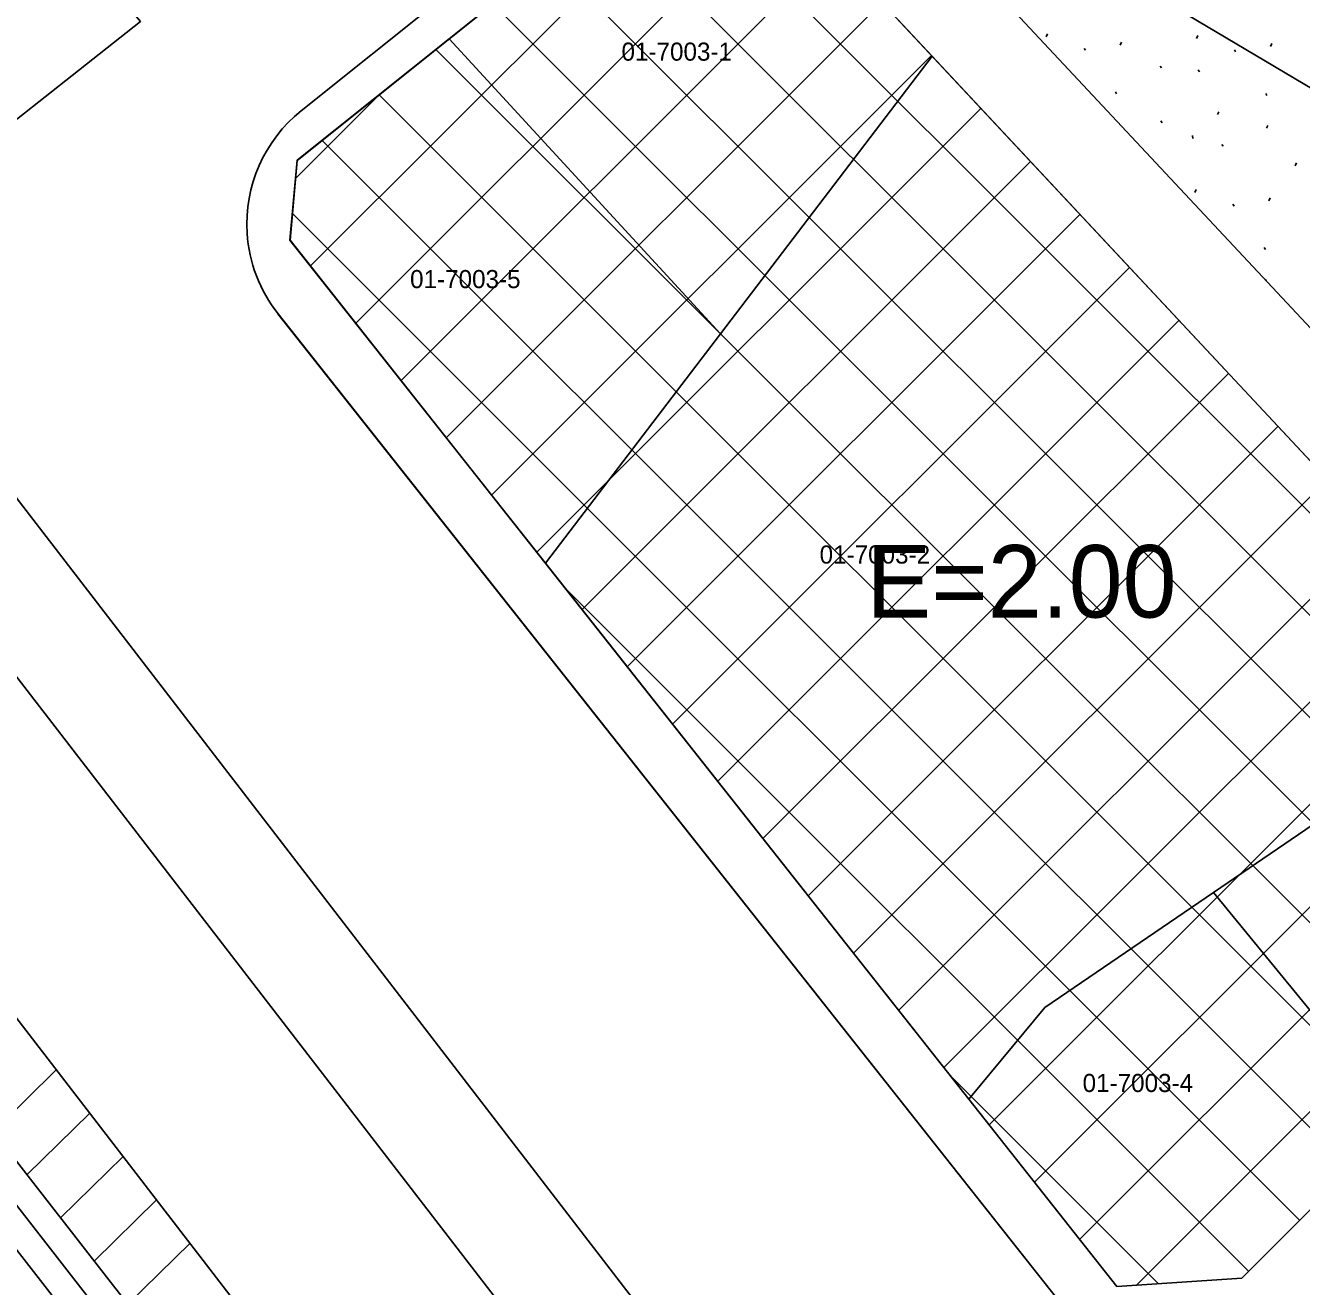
# Model space of a CAD drawing. Extents: x 413946 to 415528, y 4453939 to 4454944.
# Drawn here: x 414666.5 to 414736.9, y 4454622.3 to 4454691.9 of the extents above; entities that cross this region are included whole.
import ezdxf

# ---------------------------------------------------------------- set-up
doc = ezdxf.new("R2010")
doc.units = 0
for name, color, linetype in [('0_KADASTRO', 7, 'Continuous'), ('Level 28', 7, 'Continuous'), ('Level 29', 7, 'Continuous'), ('Level 30', 7, 'Continuous'), ('Level 34', 7, 'Continuous'), ('Level 41', 7, 'Continuous'), ('Level 53', 7, 'Continuous'), ('Level 62', 7, 'Continuous')]:
    doc.layers.add(name, color=color, linetype=linetype)

msp = doc.modelspace()

# ---------------------------------------------------------------- linework, layer by layer
at = {"layer": '0_KADASTRO'}
for points in [[(414705.59, 4454707.32), (414711.53, 4454711.44), (414720.94, 4454716.78), (414737.42, 4454727.23), (414744.54, 4454719.51), (414749.84, 4454713.87), (414763.53, 4454699.29), (414766.996, 4454695.593), (414767.59, 4454694.96), (414753, 4454679.16)], [(414689.88, 4454691.13), (414704.62, 4454702.92), (414716.53, 4454690.17), (414704.85, 4454674.85)], [(414654.74, 4454690.35), (414658.55, 4454693.35), (414666.43, 4454699.58), (414672.85, 4454692.09), (414660.82, 4454682.59)], [(414681.1, 4454680.02), (414681.5, 4454684.42), (414689.88, 4454691.13), (414704.85, 4454674.85), (414695.19, 4454662.18)], [(414695.19, 4454662.18), (414704.85, 4454674.85), (414716.53, 4454690.17), (414748.89, 4454655.51), (414732.06, 4454644.01), (414722.74, 4454637.65), (414718.56, 4454632.6)], [(414732.06, 4454644.01), (414748.89, 4454655.51), (414753.56, 4454650.51), (414754.21, 4454643.34), (414742.34, 4454631.46)], [(414718.56, 4454632.6), (414722.74, 4454637.65), (414732.06, 4454644.01), (414742.34, 4454631.46), (414733.61, 4454622.72), (414726.72, 4454622.26)]]:
    msp.add_lwpolyline(points, close=True, dxfattribs=at)
at = {"layer": 'Level 28'}
for p, q in [((414757.678, 4454653.428), (414708.537, 4454706.057)), ((414704.62, 4454702.922), (414753.563, 4454650.505))]:
    msp.add_line(p, q, dxfattribs=at)
msp.add_lwpolyline([(414754.206, 4454643.343), (414733.609, 4454622.72), (414726.724, 4454622.261)], dxfattribs=at)
at = {"layer": 'Level 29'}
for points in [[(414681.498, 4454684.416), (414698.528, 4454698.043), (414704.62, 4454702.922)], [(414726.724, 4454622.261), (414681.103, 4454680.02), (414681.498, 4454684.416)]]:
    msp.add_lwpolyline(points, dxfattribs=at)
at = {"layer": 'Level 34'}
for p, q in [((414682.235, 4454678.587), (414705.562, 4454701.914)), ((414753.735, 4454648.591), (414701.724, 4454700.602)), ((414684.731, 4454675.426), (414708.294, 4454698.989)), ((414753.766, 4454642.903), (414698.582, 4454698.087)), ((414687.228, 4454672.266), (414711.025, 4454696.063)), ((414750.939, 4454640.073), (414695.44, 4454695.572)), ((414689.724, 4454669.105), (414713.756, 4454693.138)), ((414748.113, 4454637.243), (414692.298, 4454693.058)), ((414745.286, 4454634.412), (414689.155, 4454690.543)), ((414692.22, 4454665.945), (414716.488, 4454690.212)), ((414681.408, 4454683.417), (414686.048, 4454688.057)), ((414742.46, 4454631.582), (414686.013, 4454688.029)), ((414694.717, 4454662.784), (414719.22, 4454687.287)), ((414739.633, 4454628.752), (414682.87, 4454685.514)), ((414697.213, 4454659.624), (414721.951, 4454684.362)), ((414736.806, 4454625.922), (414681.235, 4454681.493)), ((414699.709, 4454656.463), (414724.682, 4454681.436)), ((414702.206, 4454653.303), (414727.414, 4454678.511)), ((414704.702, 4454650.142), (414730.145, 4454675.586)), ((414707.198, 4454646.982), (414732.877, 4454672.66)), ((414709.695, 4454643.821), (414735.609, 4454669.735)), ((414712.191, 4454640.661), (414738.34, 4454666.81)), ((414714.687, 4454637.5), (414741.071, 4454663.884)), ((414733.98, 4454623.091), (414696.332, 4454660.739)), ((414717.184, 4454634.34), (414743.803, 4454660.959)), ((414719.68, 4454631.179), (414746.534, 4454658.034)), ((414722.176, 4454628.019), (414749.266, 4454655.108)), ((414724.673, 4454624.858), (414751.997, 4454652.182)), ((414727.805, 4454622.333), (414753.762, 4454648.29)), ((414729.001, 4454622.413), (414717.594, 4454633.82))]:
    msp.add_line(p, q, dxfattribs=at)
at = {"layer": 'Level 41'}
for p, q in [((414722.824, 4454691.236), (414722.895, 4454691.395)), ((414731.116, 4454691.151), (414731.188, 4454691.311)), ((414724.912, 4454690.599), (414724.982, 4454690.492)), ((414726.902, 4454690.786), (414726.975, 4454690.946)), ((414735.195, 4454690.702), (414735.267, 4454690.861)), ((414733.205, 4454690.514), (414733.275, 4454690.407)), ((414729.111, 4454689.627), (414729.18, 4454689.519)), ((414731.207, 4454689.413), (414731.277, 4454689.306)), ((414726.64, 4454688.199), (414726.71, 4454688.091)), ((414734.932, 4454688.114), (414735.002, 4454688.006)), ((414732.279, 4454686.948), (414732.352, 4454687.106)), ((414729.146, 4454686.596), (414729.216, 4454686.489)), ((414734.971, 4454686.192), (414735.044, 4454686.351)), ((414730.896, 4454685.787), (414730.913, 4454685.627)), ((414732.521, 4454685.301), (414732.59, 4454685.193)), ((414736.565, 4454684.115), (414736.639, 4454684.274)), ((414731.029, 4454682.642), (414731.101, 4454682.801)), ((414735.108, 4454682.192), (414735.18, 4454682.351)), ((414733.118, 4454682.004), (414733.188, 4454681.898)), ((414734.845, 4454679.605), (414734.915, 4454679.497)), ((414734.933, 4454677.788), (414734.957, 4454677.841))]:
    msp.add_line(p, q, dxfattribs=at)
at = {"layer": 'Level 53'}
for p, q in [((414513.19, 4454835.46), (414736.41, 4454545.68)), ((414664.739, 4454630.805), (414668.211, 4454634.214)), ((414666.592, 4454628.422), (414670.055, 4454631.821)), ((414668.446, 4454626.039), (414671.899, 4454629.427)), ((414670.301, 4454623.655), (414673.743, 4454627.033)), ((414672.156, 4454621.27), (414675.587, 4454624.639))]:
    msp.add_line(p, q, dxfattribs=at)
for points in [[(414423.974, 4454943.957), (414424.74, 4454942.963), (414572.056, 4454750.765), (414639.335, 4454663.459), (414685.251, 4454604.438), (414748.178, 4454522.381), (414789.332, 4454468.628), (414859.787, 4454378.078), (414913.215, 4454308.551), (414942.988, 4454270.03)], [(414421.521, 4454942.223), (414422.362, 4454941.133), (414569.678, 4454748.937), (414636.963, 4454661.623), (414682.877, 4454602.604), (414745.796, 4454520.557), (414786.956, 4454466.794), (414857.413, 4454376.242), (414910.839, 4454306.721), (414940.611, 4454268.199)], [(414423.778, 4454941.752), (414570.867, 4454749.851), (414638.149, 4454662.541), (414684.064, 4454603.521), (414746.987, 4454521.469), (414788.144, 4454467.711), (414858.6, 4454377.16), (414912.027, 4454307.636), (414941.799, 4454269.115)]]:
    msp.add_lwpolyline(points, dxfattribs=at)
at = {"layer": 'Level 62'}
for p, q in [((414527.05, 4454846.14), (414750.3, 4454556.32)), ((414522.3, 4454842.48), (414745.54, 4454552.67))]:
    msp.add_line(p, q, dxfattribs=at)
for points in [[(414681.723, 4454687.157), (414697.278, 4454699.604), (414721.091, 4454718.676)], [(414724.357, 4454620.395), (414680.43, 4454675.941)], [(414724.37, 4454620.402), (414680.445, 4454675.949)]]:
    msp.add_lwpolyline(points, dxfattribs=at)
for start, end in [(128.66177, 183.7014), (183.7014, 218.33609)]:
    msp.add_arc((414686.72, 4454680.911), 8, start, end, dxfattribs=at)

# ---------------------------------------------------------------- texts
at = {"layer": '0_KADASTRO'}
for s, p in [('01-7003-1', (414699.392, 4454689.921)), ('01-7003-5', (414687.727, 4454677.364)), ('01-7003-2', (414710.322, 4454662.159)), ('01-7003-4', (414724.831, 4454632.988))]:
    msp.add_text(s, height=1, dxfattribs=at).set_placement(p)
at = {"layer": 'Level 30'}
msp.add_text('E=2.00', height=4, dxfattribs=at).set_placement((414712.911, 4454659.181))

doc.saveas('drawing.dxf')
